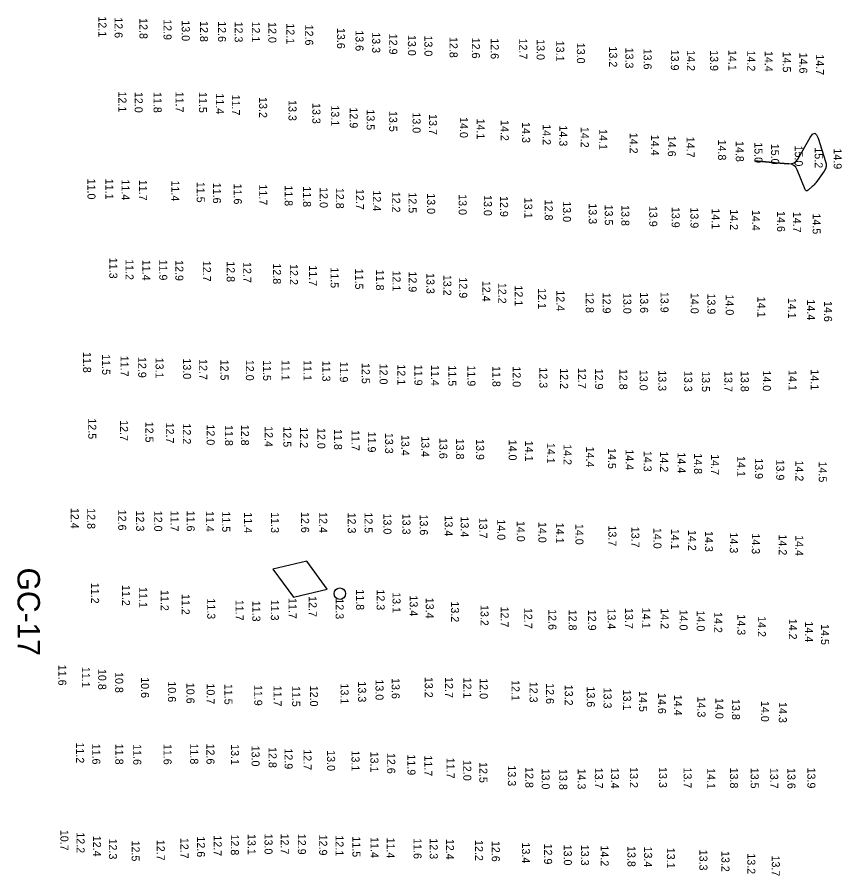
# Model space of a CAD drawing. Extents: x 988130 to 1132882, y 654656 to 841453.
# Drawn here: x 1109587 to 1110102, y 667502 to 668038 of the extents above; entities that cross this region are included whole.
import ezdxf

# ---------------------------------------------------------------- set-up
doc = ezdxf.new("R2010")
doc.units = 0
for name, color, linetype in [('V-CHAN-NAID', 7, 'Continuous'), ('V-TOPO-MAJR', 7, 'Continuous'), ('V-TOPO-SOUN', 7, 'Continuous')]:
    doc.layers.add(name, color=color, linetype=linetype)

msp = doc.modelspace()

# ---------------------------------------------------------------- linework, layer by layer
at = {"layer": 'V-CHAN-NAID'}
msp.add_lwpolyline([(1109780.54, 667681.42), (1109767.73, 667698.86), (1109746.71, 667693.74), (1109759.52, 667676.3)], close=True, dxfattribs=at)
msp.add_circle((1109788.43, 667678.55), 3.6, dxfattribs=at)
at = {"layer": 'V-TOPO-MAJR'}
msp.add_lwpolyline([(1110057.51, 667947.81), (1110058.81, 667947.71), (1110060.11, 667947.61), (1110068.61, 667946.97), (1110070.34, 667947.05), (1110071.85, 667947.56), (1110073.12, 667948.52), (1110074.16, 667949.91), (1110081.92, 667963.41), (1110083.4, 667965.39), (1110084.72, 667965.97), (1110085.9, 667965.13), (1110086.92, 667962.88), (1110091.54, 667948.47), (1110091.88, 667946.83), (1110091.83, 667945.25), (1110091.38, 667943.74), (1110090.54, 667942.29), (1110085.32, 667935.1), (1110084.82, 667934.45), (1110084.28, 667933.83), (1110083.7, 667933.24), (1110083.09, 667932.69), (1110080.58, 667930.54), (1110079.99, 667930.16), (1110079.48, 667930.11), (1110079.05, 667930.39), (1110078.69, 667930.99), (1110073.71, 667943.25), (1110072.87, 667944.77), (1110071.73, 667945.9), (1110070.32, 667946.63), (1110068.61, 667946.97), (1110060.11, 667947.61), (1110058.81, 667947.71), (1110057.51, 667947.81), (1110056.21, 667947.92), (1110047.14, 667948.76), (1110056.21, 667947.92)], close=True, dxfattribs=at)

# ---------------------------------------------------------------- texts
at = {"layer": 'V-CHAN-NAID'}
msp.add_text('GC-17', height=14, rotation=270, dxfattribs=at).set_placement((1109587.3, 667694.82))
at = {"layer": 'V-TOPO-SOUN'}
for s, p in [('12.1 ', (1109637.81, 668039.01)), ('12.6 ', (1109647.87, 668038.45)), ('12.8 ', (1109663.42, 668037.91)), ('12.9 ', (1109678.43, 668037.25)), ('13.0 ', (1109689.79, 668036.54)), ('12.8 ', (1109701.17, 668036.07)), ('12.6 ', (1109712.39, 668035.97)), ('12.3 ', (1109722.79, 668035.76)), ('12.1 ', (1109733.56, 668035.78)), ('12.0 ', (1109743.81, 668035.41)), ('12.1 ', (1109755.12, 668034.67)), ('12.6 ', (1109766.81, 668033.85)), ('13.6 ', (1109786.65, 668031.78)), ('13.6 ', (1109798.2, 668030.31)), ('13.3 ', (1109808.6, 668029.1)), ('12.9 ', (1109819.27, 668028.19)), ('13.0 ', (1109830.89, 668027.43)), ('13.0 ', (1109841.19, 668027.07)), ('12.8 ', (1109856.89, 668026.14)), ('12.6 ', (1109870.83, 668025.72)), ('12.6 ', (1109882.58, 668025.31)), ('12.7 ', (1109900.33, 668025.17)), ('13.0 ', (1109911.22, 668024.76)), ('13.1 ', (1109923.41, 668023.82)), ('13.0 ', (1109936.34, 668022.53)), ('13.2 ', (1109956.46, 668020.21)), ('13.3 ', (1109966.6, 668019.49)), ('13.6 ', (1109977.97, 668018.86)), ('13.9 ', (1109994.98, 668018.21)), ('14.2 ', (1110005.01, 668017.9)), ('13.9 ', (1110019.48, 668017.89)), ('14.1 ', (1110030.89, 668018.04)), ('14.2 ', (1110042.6, 668017.7)), ('14.4 ', (1110053.51, 668017.42)), ('14.5 ', (1110064.83, 668017.01)), ('14.6 ', (1110075.13, 668016.37)), ('14.7 ', (1110085.49, 668015.31)), ('12.1 ', (1109650.29, 667992.09)), ('12.0 ', (1109660.41, 667991.83)), ('11.8 ', (1109672.2, 667991.79)), ('11.7 ', (1109685.95, 667992.02)), ('11.5 ', (1109700.52, 667991.79)), ('11.4 ', (1109711.09, 667990.96)), ('11.7 ', (1109721.08, 667990.17)), ('13.2 ', (1109738.06, 667988.58)), ('13.3 ', (1109756.4, 667986.73)), ('13.3 ', (1109771.31, 667984.9)), ('13.1 ', (1109783.02, 667983.43)), ('12.9 ', (1109794.59, 667982.13)), ('13.5 ', (1109805.14, 667980.92)), ('13.5 ', (1109819.22, 667979.97)), ('13.0 ', (1109833.81, 667979.05)), ('13.7 ', (1109844.09, 667977.99)), ('14.0 ', (1109863.32, 667976.1)), ('14.1 ', (1109873.81, 667975.21)), ('14.2 ', (1109888.82, 667974.29)), ('14.3 ', (1109902.17, 667972.97)), ('14.2 ', (1109915.04, 667971.67)), ('14.3 ', (1109925.39, 667970.89)), ('14.2 ', (1109938.79, 667970.01)), ('14.1 ', (1109950.24, 667968.66)), ('14.2 ', (1109969.28, 667966.34)), ('14.4 ', (1109982.66, 667965.05)), ('14.6 ', (1109993.1, 667964.44)), ('14.7 ', (1110004.73, 667963.82)), ('14.8 ', (1110024.44, 667962.08)), ('14.8 ', (1110035.49, 667961.2)), ('15.0 ', (1110047.14, 667960.43)), ('15.0 ', (1110057.51, 667959.47)), ('15.0 ', (1110072.31, 667958.36)), ('15.2 ', (1110084.71, 667957.23)), ('14.9 ', (1110096.56, 667956.58)), ('11.0 ', (1109630.96, 667937.7)), ('11.1 ', (1109642.11, 667937.66)), ('11.4 ', (1109652.22, 667937.21)), ('11.7 ', (1109663.16, 667936.95)), ('11.4 ', (1109683.3, 667936.52)), ('11.5 ', (1109699.11, 667935.7)), ('11.6 ', (1109709.26, 667935.15)), ('11.6 ', (1109722.25, 667934.6)), ('11.7 ', (1109738.12, 667934.04)), ('11.8 ', (1109753.98, 667933.51)), ('11.8 ', (1109765.44, 667932.9)), ('12.0 ', (1109775.88, 667932.36)), ('12.8 ', (1109785.96, 667931.93)), ('12.7 ', (1109798.46, 667931.23)), ('12.4 ', (1109809.02, 667930.37)), ('12.2 ', (1109821.08, 667929.53)), ('12.5 ', (1109831.32, 667929.11)), ('13.0 ', (1109842.9, 667928.58)), ('13.0 ', (1109862.56, 667927.98)), ('13.0 ', (1109878.27, 667927.42)), ('12.9 ', (1109888.4, 667926.82)), ('13.1 ', (1109903.53, 667925.79)), ('12.8 ', (1109916.29, 667924.55)), ('13.0 ', (1109927.62, 667923.56)), ('13.3 ', (1109943.74, 667922.28)), ('13.5 ', (1109953.76, 667921.48)), ('13.8 ', (1109964.09, 667921.15)), ('13.9 ', (1109981.47, 667920.65)), ('13.9 ', (1109995.46, 667920.05)), ('13.9 ', (1110007.2, 667919.73)), ('14.1 ', (1110020.51, 667919.12)), ('14.2 ', (1110031.86, 667918.59)), ('14.4 ', (1110045.58, 667918.16)), ('14.6 ', (1110061.24, 667917.43)), ('14.7 ', (1110071.23, 667916.98)), ('14.5 ', (1110083.44, 667915.94)), ('11.3 ', (1109644.61, 667888.27)), ('11.2 ', (1109654.71, 667887.4)), ('11.4 ', (1109665.24, 667887)), ('11.9 ', (1109675.74, 667887.15)), ('12.9 ', (1109685.79, 667886.81)), ('12.7 ', (1109702.98, 667886.38)), ('12.8 ', (1109717.86, 667886.09)), ('12.7 ', (1109728.16, 667885.61)), ('12.8 ', (1109746.73, 667884.78)), ('12.2 ', (1109757.24, 667884.31)), ('11.7 ', (1109769.2, 667883.59)), ('11.5 ', (1109782.66, 667882.34)), ('11.5 ', (1109797.98, 667881.5)), ('11.8 ', (1109811, 667880.84)), ('12.1 ', (1109821.31, 667880.3)), ('12.9 ', (1109831.37, 667879.75)), ('13.3 ', (1109842.48, 667878.74)), ('13.2 ', (1109853.02, 667877.63)), ('12.9 ', (1109862.89, 667876.02)), ('12.4 ', (1109877.34, 667873.88)), ('12.2 ', (1109887.27, 667872.63)), ('12.1 ', (1109897.54, 667870.99)), ('12.1 ', (1109912.15, 667869.28)), ('12.4 ', (1109923.61, 667867.94)), ('12.8 ', (1109941.86, 667866.8)), ('12.9 ', (1109952.42, 667866.48)), ('13.0 ', (1109965.27, 667866.34)), ('13.6 ', (1109975.8, 667866.74)), ('13.9 ', (1109988.53, 667866.99)), ('14.0 ', (1110007.32, 667866.36)), ('13.9 ', (1110017.78, 667865.97)), ('14.0 ', (1110029.21, 667865.35)), ('14.1 ', (1110048.96, 667863.99)), ('14.1 ', (1110068.15, 667863.27)), ('14.4 ', (1110079.91, 667862.26)), ('14.6 ', (1110090.56, 667861.26)), ('11.8 ', (1109628.22, 667829.47)), ('11.5 ', (1109640.12, 667828.07)), ('11.7 ', (1109651.59, 667827.08)), ('12.9 ', (1109662.63, 667826.32)), ('13.1 ', (1109673.45, 667825.92)), ('13.0 ', (1109690.61, 667825.44)), ('12.7 ', (1109700.7, 667825)), ('12.5 ', (1109713.96, 667824.65)), ('12.0 ', (1109729.78, 667824.54)), ('11.5 ', (1109740.55, 667824.35)), ('11.1 ', (1109752.05, 667824.5)), ('11.1 ', (1109765.8, 667824.42)), ('11.3 ', (1109777.48, 667824.01)), ('11.9 ', (1109788.46, 667823.47)), ('12.5 ', (1109802.11, 667822.58)), ('12.0 ', (1109813.22, 667822.16)), ('12.1 ', (1109824.33, 667821.71)), ('11.9 ', (1109834.96, 667821.48)), ('11.4 ', (1109845.39, 667821.33)), ('11.5 ', (1109856.1, 667821.05)), ('11.9 ', (1109868.06, 667821.02)), ('11.8 ', (1109883.63, 667820.68)), ('12.0 ', (1109896.26, 667820.48)), ('12.3 ', (1109912.94, 667819.86)), ('12.2 ', (1109925.86, 667819.29)), ('12.7 ', (1109937.07, 667819.52)), ('12.9 ', (1109947.66, 667819.08)), ('12.8 ', (1109962.82, 667818.89)), ('13.0 ', (1109975.49, 667818.31)), ('13.3 ', (1109987.13, 667818)), ('13.3 ', (1110003.29, 667817.58)), ('13.5 ', (1110014.33, 667817.47)), ('13.7 ', (1110028.36, 667817.51)), ('13.8 ', (1110038.6, 667817.59)), ('14.0 ', (1110052.36, 667817.93)), ('14.1 ', (1110068.44, 667818.21)), ('14.1 ', (1110082.27, 667818.6)), ('12.5 ', (1109631.45, 667788.02)), ('12.7 ', (1109651.29, 667786.88)), ('12.5 ', (1109667.11, 667785.92)), ('12.7 ', (1109679.93, 667785.35)), ('12.2 ', (1109690.49, 667784.82)), ('12.0 ', (1109705.32, 667784.2)), ('11.8 ', (1109716.74, 667783.82)), ('12.8 ', (1109726.77, 667784)), ('12.4 ', (1109741.58, 667783.13)), ('12.5 ', (1109753.18, 667782.96)), ('12.2 ', (1109763.56, 667782.42)), ('12.0 ', (1109774.39, 667782)), ('11.8 ', (1109784.82, 667781.34)), ('11.7 ', (1109795.71, 667780.73)), ('11.9 ', (1109805.9, 667779.74)), ('13.3 ', (1109816.68, 667778.95)), ('13.4 ', (1109826.79, 667777.65)), ('13.4 ', (1109839.27, 667776.86)), ('13.6 ', (1109850.49, 667775.76)), ('13.8 ', (1109860.94, 667775.34)), ('13.9 ', (1109873.46, 667775.03)), ('14.0 ', (1109893.75, 667774.69)), ('14.1 ', (1109903.98, 667774.08)), ('14.1 ', (1109917.61, 667772.72)), ('14.2 ', (1109928.02, 667771.87)), ('14.4 ', (1109942.11, 667770.37)), ('14.5 ', (1109955.8, 667769.43)), ('14.4 ', (1109966.74, 667768.69)), ('14.3 ', (1109977.98, 667767.72)), ('14.2 ', (1109988.29, 667767.38)), ('14.4 ', (1109999.15, 667766.76)), ('14.8 ', (1110009.46, 667766.21)), ('14.7 ', (1110020.08, 667765.62)), ('14.1 ', (1110036.35, 667764.45)), ('13.9 ', (1110047.43, 667763.12)), ('13.9 ', (1110060.7, 667762.29)), ('14.2 ', (1110072.71, 667761.7)), ('14.5 ', (1110087.26, 667761.06)), ('12.4 ', (1109620.57, 667732.11)), ('12.8 ', (1109630.82, 667731.91)), ('12.6 ', (1109650.15, 667730.98)), ('12.3 ', (1109661.33, 667730.44)), ('12.0 ', (1109672.6, 667730.33)), ('11.7 ', (1109682.81, 667730.4)), ('11.6 ', (1109692.86, 667730.37)), ('11.4 ', (1109704.81, 667730.16)), ('11.5 ', (1109715.03, 667729.93)), ('11.4 ', (1109728.68, 667729.35)), ('11.3 ', (1109745.45, 667729.42)), ('12.6 ', (1109764.26, 667729.54)), ('12.4 ', (1109775.57, 667729.47)), ('12.3 ', (1109793.39, 667729.17)), ('12.5 ', (1109803.84, 667729.27)), ('13.0 ', (1109815.62, 667728.6)), ('13.3 ', (1109827.49, 667728.46)), ('13.6 ', (1109838.33, 667727.97)), ('13.4 ', (1109853.81, 667727.4)), ('13.4 ', (1109863.86, 667726.76)), ('13.7 ', (1109875.36, 667725.98)), ('14.0 ', (1109886.66, 667725)), ('14.0 ', (1109898.85, 667723.99)), ('14.0 ', (1109912.3, 667723.33)), ('14.1 ', (1109923.24, 667722.83)), ('14.0 ', (1109935.42, 667722.13)), ('13.7 ', (1109956, 667721.12)), ('13.7 ', (1109970.33, 667720.31)), ('14.0 ', (1109984.11, 667719.63)), ('14.1 ', (1109995.1, 667719.03)), ('14.2 ', (1110005.72, 667718.34)), ('14.3 ', (1110016.26, 667717.63)), ('14.3 ', (1110031.77, 667716.77)), ('14.3 ', (1110045.49, 667716.22)), ('14.2 ', (1110062.32, 667715.5)), ('14.4 ', (1110072.67, 667715.05)), ('11.2 ', (1109633.21, 667685.33)), ('11.2 ', (1109652.49, 667683.98)), ('11.1 ', (1109663.25, 667682.67)), ('11.2 ', (1109676.66, 667680.83)), ('11.8 ', (1109798.58, 667681.26)), ('12.3 ', (1109811.38, 667681.2)), ('11.2 ', (1109689.75, 667678.36)), ('11.3 ', (1109705.68, 667675.61)), ('11.7 ', (1109723.37, 667674.7)), ('11.3 ', (1109745.38, 667674.76)), ('11.7 ', (1109756.47, 667675.86)), ('12.7 ', (1109768.99, 667677)), ('12.3 ', (1109785.81, 667675.63)), ('13.1 ', (1109821.31, 667679.46)), ('13.4 ', (1109831.99, 667677.47)), ('13.4 ', (1109842.02, 667676.03)), ('11.3 ', (1109733.82, 667674.11)), ('13.2 ', (1109857.78, 667673.71)), ('13.2 ', (1109876.22, 667671.46)), ('12.7 ', (1109888.78, 667670.48)), ('12.7 ', (1109903.48, 667669.66)), ('12.6 ', (1109918.55, 667668.85)), ('13.4 ', (1109955.51, 667669.28)), ('13.7 ', (1109966.38, 667669.61)), ('14.1 ', (1109977.1, 667669.79)), ('14.2 ', (1109988.64, 667669.46)), ('12.8 ', (1109931.22, 667668.54)), ('12.9 ', (1109943.36, 667668.51)), ('14.0 ', (1110000.38, 667668.6)), ('14.0 ', (1110011.11, 667668.02)), ('14.2 ', (1110021.99, 667667.06)), ('14.3 ', (1110036.47, 667665.63)), ('14.2 ', (1110049.24, 667664.5)), ('14.2 ', (1110068.62, 667662.9)), ('14.4 ', (1110078.71, 667661.21)), ('14.5 ', (1110088.67, 667659.52)), ('11.6 ', (1109612.76, 667634.16)), ('11.1 ', (1109627.48, 667632.84)), ('10.8 ', (1109637.66, 667631.51)), ('10.8 ', (1109648.25, 667629.6)), ('10.6 ', (1109664.39, 667626.38)), ('13.2 ', (1109841.42, 667626.59)), ('12.7 ', (1109854.09, 667626.45)), ('12.1 ', (1109865.51, 667626.15)), ('10.6 ', (1109681.18, 667623.77)), ('10.6 ', (1109692.72, 667622.89)), ('10.7 ', (1109705.32, 667622.48)), ('11.5 ', (1109716.42, 667622.23)), ('11.9 ', (1109735.02, 667621.57)), ('11.7 ', (1109747.09, 667621.13)), ('11.5 ', (1109758.68, 667620.93)), ('12.0 ', (1109769.81, 667621.09)), ('13.1 ', (1109788.89, 667622.47)), ('13.3 ', (1109799.83, 667623.72)), ('13.0 ', (1109810.7, 667625)), ('13.6 ', (1109820.78, 667625.85)), ('12.0 ', (1109875.71, 667625.75)), ('12.1 ', (1109895.55, 667624.61)), ('12.3 ', (1109906.81, 667623.56)), ('12.6 ', (1109917.06, 667622.65)), ('13.2 ', (1109928.81, 667621.69)), ('13.6 ', (1109942.53, 667620.6)), ('13.3 ', (1109952.97, 667619.88)), ('13.1 ', (1109965.18, 667618.63)), ('14.5 ', (1109975.16, 667617.75)), ('14.6 ', (1109986.94, 667616.51)), ('14.4 ', (1109996.94, 667615.41)), ('14.3 ', (1110011.57, 667614.31)), ('14.0 ', (1110022.76, 667613.39)), ('13.8 ', (1110033.09, 667612.73)), ('14.0 ', (1110051.23, 667611.57)), ('14.3 ', (1110062.34, 667610.86)), ('11.2 ', (1109623.88, 667585.61)), ('11.6 ', (1109633.96, 667584.91)), ('11.8 ', (1109648.33, 667584.81)), ('11.6 ', (1109659.53, 667584.56)), ('11.6 ', (1109678.44, 667584.74)), ('11.8 ', (1109695.06, 667585)), ('12.6 ', (1109705.21, 667584.95)), ('13.1 ', (1109720.54, 667584.58)), ('13.0 ', (1109733.35, 667583.67)), ('12.8 ', (1109743.99, 667582.76)), ('12.9 ', (1109753.96, 667581.93)), ('12.7 ', (1109765.75, 667581.34)), ('13.0 ', (1109780.46, 667580.81)), ('13.1 ', (1109795.7, 667580.63)), ('13.1 ', (1109807.5, 667579.92)), ('12.6 ', (1109818, 667579.1)), ('11.9 ', (1109830.63, 667578.17)), ('11.7 ', (1109841.14, 667577.54)), ('11.7 ', (1109854.99, 667576.08)), ('12.0 ', (1109865.43, 667574.74)), ('12.5 ', (1109875.49, 667573.4)), ('13.3 ', (1109893.29, 667571.32)), ('12.8 ', (1109904.16, 667570.27)), ('13.0 ', (1109914.38, 667569.35)), ('13.8 ', (1109925.32, 667569.03)), ('14.3 ', (1109936.82, 667569.35)), ('13.7 ', (1109947.54, 667569.84)), ('13.4 ', (1109957.59, 667569.87)), ('13.2 ', (1109969.42, 667570.24)), ('13.3 ', (1109987.52, 667570.28)), ('13.7 ', (1110002.92, 667570)), ('14.1 ', (1110017.64, 667569.6)), ('13.8 ', (1110031.9, 667569.95)), ('13.5 ', (1110044.79, 667569.85)), ('13.7 ', (1110056.93, 667569.79)), ('13.6 ', (1110067.72, 667569.67)), ('13.9 ', (1110080.15, 667569.96)), ('10.7 ', (1109614.07, 667531.09)), ('12.2 ', (1109624.18, 667529.52)), ('12.4 ', (1109634.42, 667527.41)), ('12.3 ', (1109644.35, 667525.63)), ('12.5 ', (1109658.51, 667524.39)), ('12.7 ', (1109674.19, 667524.86)), ('12.7 ', (1109689, 667526.09)), ('12.6 ', (1109699.28, 667526.97)), ('12.7 ', (1109709.7, 667527.65)), ('12.8 ', (1109720.41, 667528.16)), ('13.1 ', (1109730.91, 667528.5)), ('13.0 ', (1109741.44, 667528.76)), ('12.7 ', (1109751.58, 667528.74)), ('12.9 ', (1109762.23, 667528.6)), ('12.9 ', (1109775.54, 667528.09)), ('12.1 ', (1109785.72, 667527.65)), ('11.5 ', (1109796.26, 667527.03)), ('11.4 ', (1109807.61, 667526.56)), ('11.4 ', (1109817.7, 667526.26)), ('11.6 ', (1109834.4, 667525.89)), ('12.3 ', (1109844.51, 667525.76)), ('12.4 ', (1109854.65, 667525.44)), ('12.2 ', (1109872.79, 667524.72)), ('12.6 ', (1109883.23, 667524.17)), ('13.4 ', (1109902.08, 667523.19)), ('12.9 ', (1109915.89, 667522.5)), ('13.0 ', (1109928.17, 667521.84)), ('13.3 ', (1109938.88, 667521.77)), ('14.2 ', (1109951.16, 667521.36)), ('13.8 ', (1109967.91, 667520.96)), ('13.4 ', (1109978.29, 667520.66)), ('13.1 ', (1109992.49, 667519.92)), ('13.3 ', (1110012.79, 667518.69)), ('13.2 ', (1110026.54, 667517.86)), ('13.2 ', (1110042.69, 667516.42)), ('13.7 ', (1110057.96, 667515.04))]:
    msp.add_text(s, height=5, rotation=270, dxfattribs=at).set_placement(p)

doc.saveas('drawing.dxf')
